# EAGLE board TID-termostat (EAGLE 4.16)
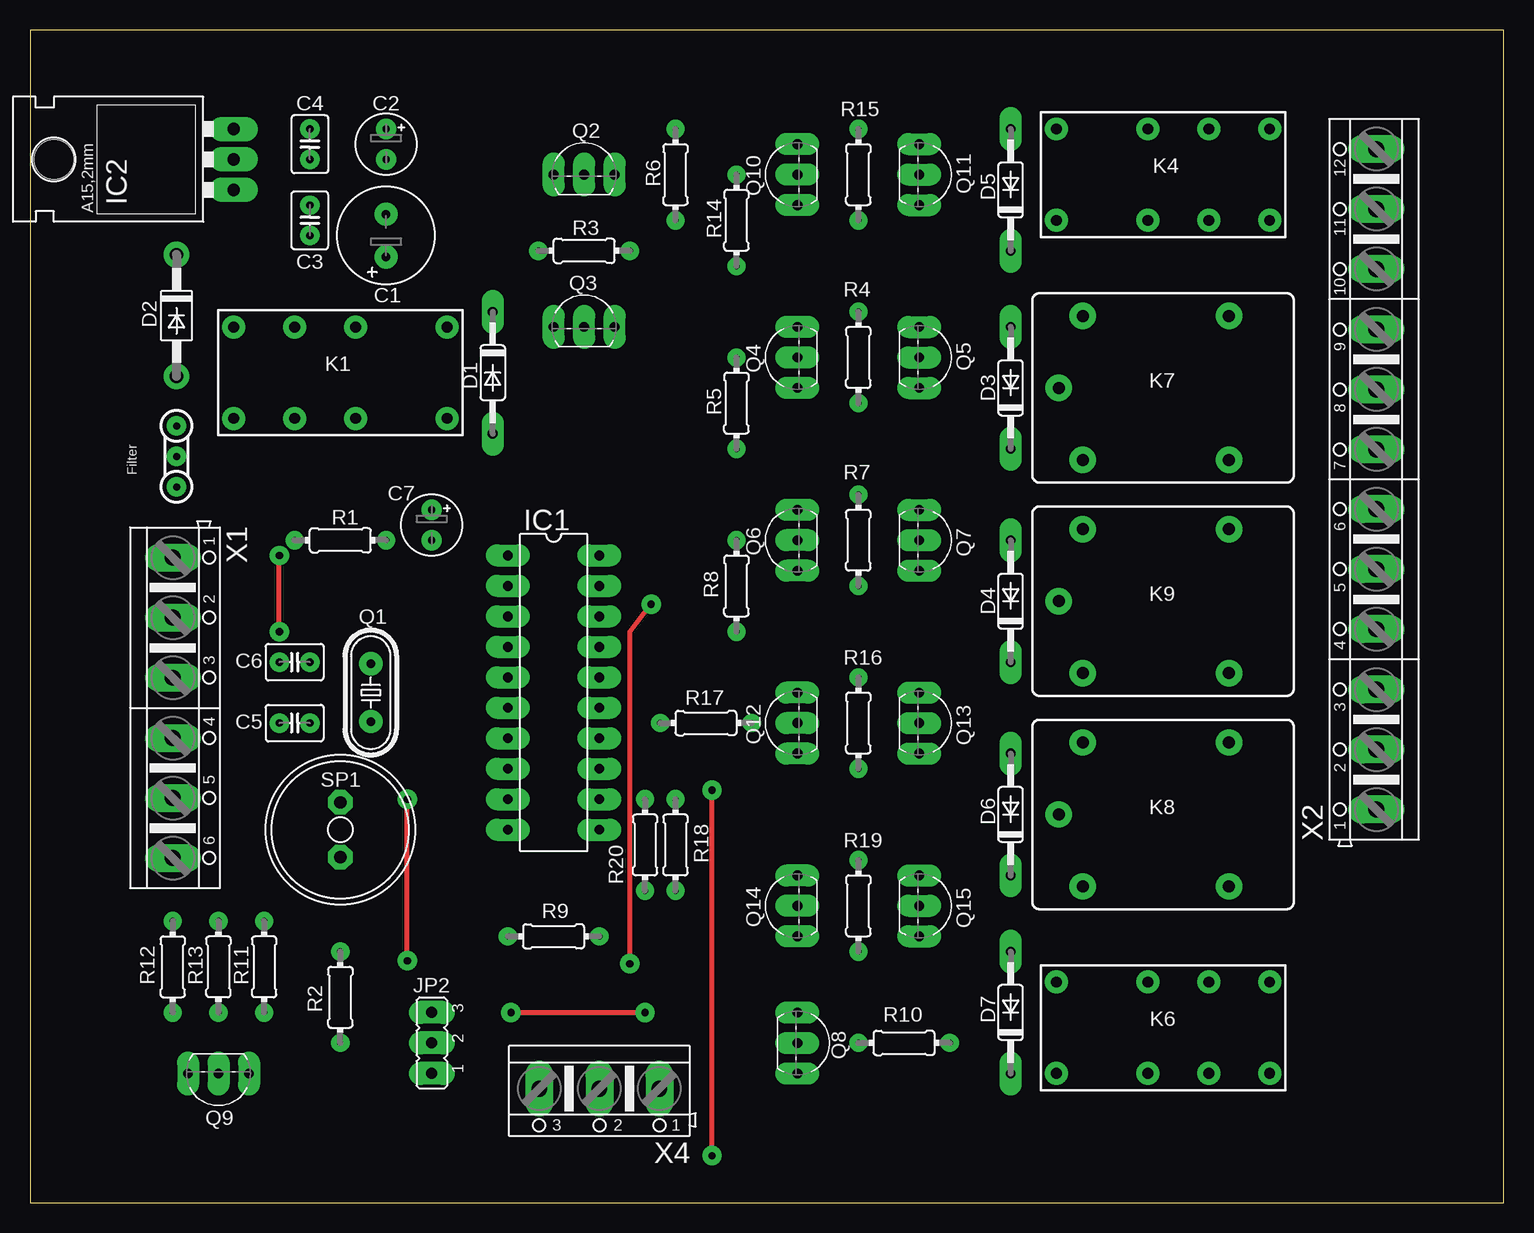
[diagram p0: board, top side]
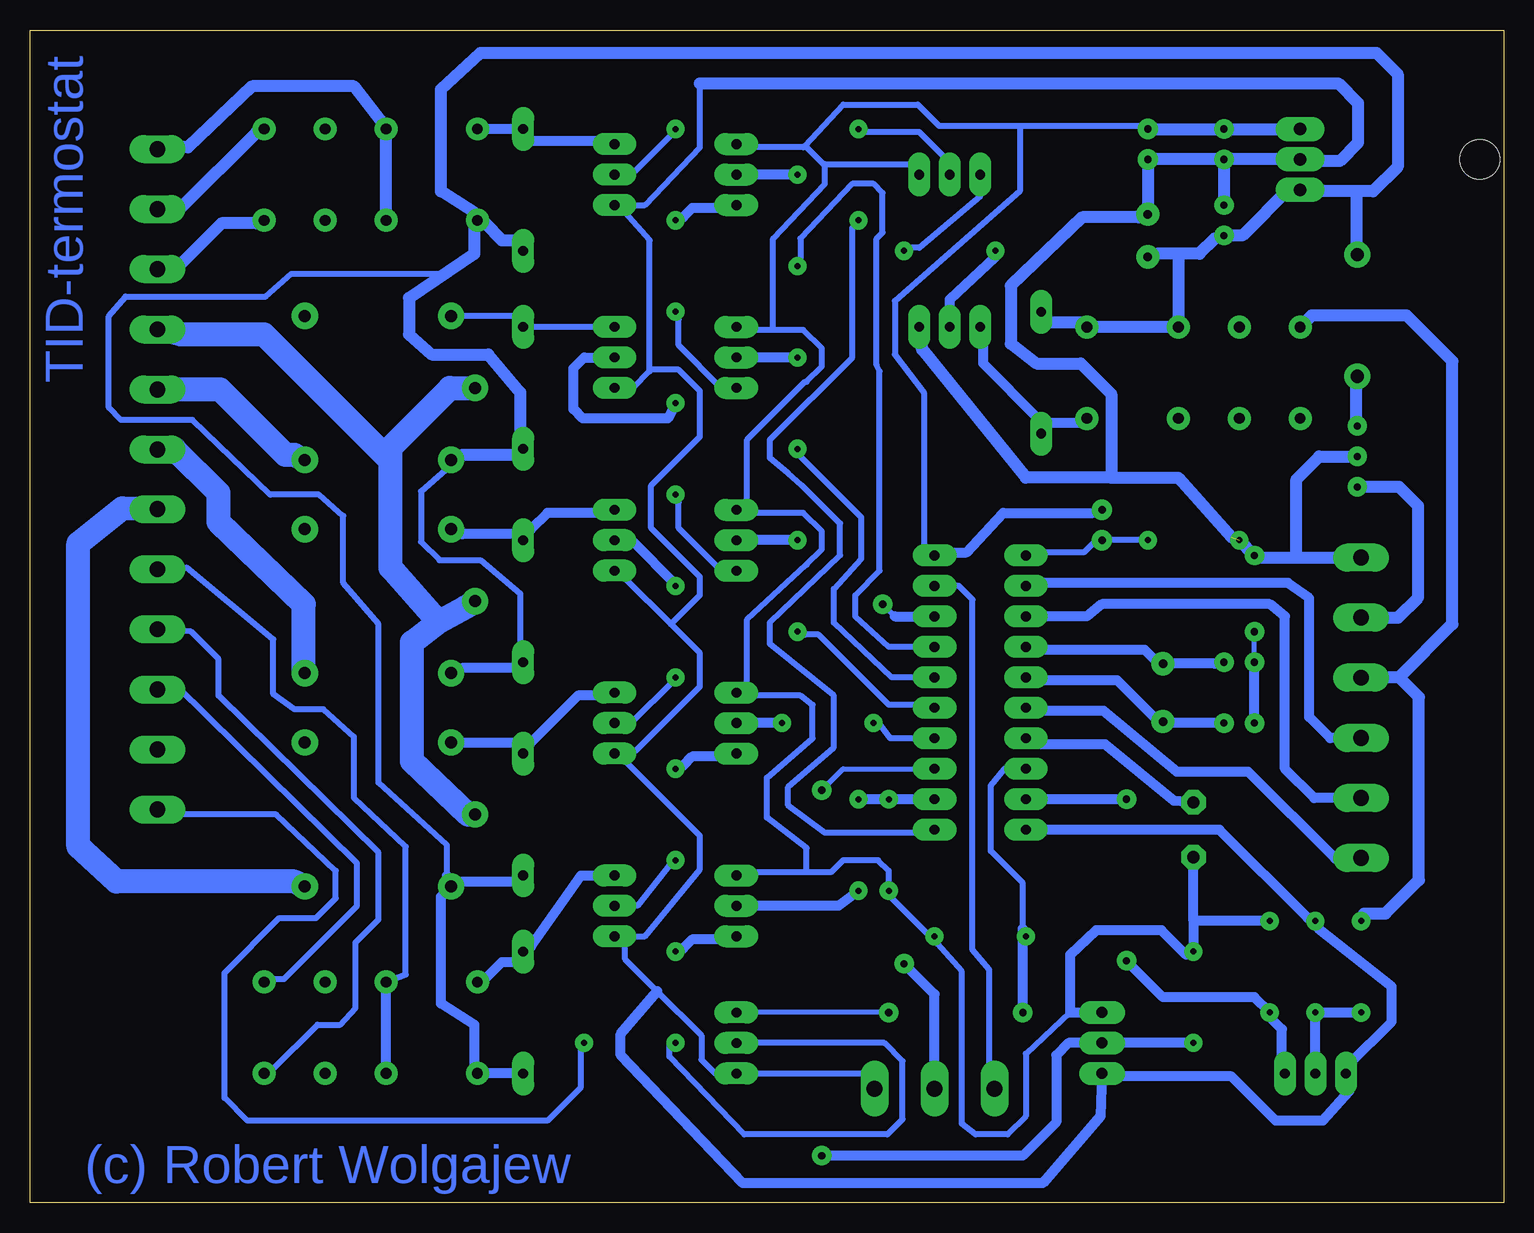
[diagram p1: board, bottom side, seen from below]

Size 122.86 x 97.78 mm. Coordinates in mm from the lower left corner, seen from the top.
Outline: 0,0 122.86,0 122.86,97.78 0,97.78 0,0
Copper layers (1*16): Top 0.035mm / dielectric 1.5mm / Bottom 0.035mm
Design rules "default": minimum track width 20mil, minimum drill 24mil, track to track 40mil, track to pad 40mil, pad to pad 40mil, via to via 40mil, smd to smd 8mil, copper to edge 20mil, drill to drill 25mil, minimum pad ring 20mil, minimum via ring 20mil, stop-mask expansion 4mil, vias tented up to drill 0mil, thermal gap 10mil
Net classes: 1 moja: width 2 mm, clearance 1 mm

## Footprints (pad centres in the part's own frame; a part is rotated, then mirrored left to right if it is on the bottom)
E3,5-8 = drill 0.7 pad 1.93 round: + -1.778,0; - 1.778,0
E2,5-5 = drill 0.6 pad 1.676 round: + -1.27,0; - 1.27,0
C2.5-3 = drill 0.6 pad 1.6 round: 1 -1.27,0; 2 1.27,0
DO35-10 = drill 0.813 long: A 5.08,0; C -5.08,0
DO41-10 = drill 1.118 round: A 5.08,0; C -5.08,0
FILTRDSS = drill 0.6 pad 1.422 round: GND -8.89,5.08; IN -11.43,5.08; OUT -6.35,5.08
DIL20 = drill 0.813 long: 1 -11.43,-3.81; 2 -8.89,-3.81; 3 -6.35,-3.81; 4 -3.81,-3.81; 5 -1.27,-3.81; 6 1.27,-3.81; 7 3.81,-3.81; 8 6.35,-3.81; 9 8.89,-3.81; 10 11.43,-3.81; 11 11.43,3.81; 12 8.89,3.81; 13 6.35,3.81; 14 3.81,3.81; 15 1.27,3.81; 16 -1.27,3.81; 17 -3.81,3.81; 18 -6.35,3.81; 19 -8.89,3.81; 20 -11.43,3.81
78XXL = drill 1.016 long: GND 0,-3.81; IN -2.54,-3.81; OUT 2.54,-3.81 | hole 3.302: 0,11.176
JP2 = drill 0.914 long: 1 -2.54,0; 2 0,0; 3 2.54,0
DS-BT = drill 0.9 round: 1 -8.89,-3.81; 4 -1.27,-3.81; 6 3.81,-3.81; 8 8.89,-3.81; 9 8.89,3.81; 11 3.81,3.81; 13 -1.27,3.81; 16 -8.89,3.81
JS-M = drill 1 pad 2.184 round: 1 6.7,6; 2 6.7,-6; C 8.7,0; NC -5.5,-6; NO -5.5,6
HC49/S = drill 0.7 pad 1.93 round: 1 -2.413,0; 2 2.413,0
TO92-EBC = drill 0.813 long: B 0,-1.27; C -2.54,-1.27; E 2.54,-1.27
0204/7 = drill 0.5 pad 1.499 round: 1 -3.81,0; 2 3.81,0
AL11P = drill 1.016 pad 1.905 octagon: + 2.286,0; - -2.286,0
AK500/6 = drill 1.321 long: 1 -12.522,0; 2 -7.518,0; 3 -2.515,0; 4 2.515,0; 5 7.518,0; 6 12.522,0
AK500/12 = drill 1.321 long: 1 -27.534,0; 2 -22.53,0; 3 -17.526,0; 4 -12.497,0; 5 -7.493,0; 6 -2.489,0; 7 2.489,0; 8 7.493,0; 9 12.497,0; 10 17.526,0; 11 22.53,0; 12 27.534,0
AK500/3 = drill 1.321 long: 1 -5.004,0; 2 0,0; 3 5.004,0

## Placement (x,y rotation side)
C1  470uF  [E3,5-8]  29.68,80.64 90 top
C2  220uF  [E2,5-5]  29.68,88.26 270 top
C3  100nF  [C2.5-3]  23.33,81.91 90 top
C4  100nF  [C2.5-3]  23.33,88.26 270 top
C5  33pF  [C2.5-3]  22.06,40 0 top
C6  33pF  [C2.5-3]  22.06,45.08 0 top
C7  10uF  [E2,5-5]  33.49,56.51 270 top
D1  1N4148  [DO35-10]  38.57,69.21 270 top
D2  1N4004  [DO41-10]  12.22,73.97 270 top
D3  1N4148  [DO35-10]  81.75,67.94 90 top
D4  1N4148  [DO35-10]  81.75,50.16 90 top
D5  1N4148  [DO35-10]  81.75,84.45 90 top
D6  1N4148  [DO35-10]  81.75,32.38 90 top
D7  1N4148  [DO35-10]  81.75,15.87 90 top
FT1  DSS306-55F223  [FILTRDSS]  17.3,71.11 90 top
IC1  AT89C4051P  [DIL20]  43.65,42.54 270 top
IC2  7805  [78XXL]  13.17,86.99 90 top
JP2  DS1820  [JP2]  33.49,13.33 90 top
K1  Wewn_AA  [DS-BT]  25.87,69.21 180 top
K4  Klima  [DS-BT]  94.45,85.72 0 top
K6  Swiatla  [DS-BT]  94.45,14.6 0 top
K7  Stopien 1  [JS-M]  94.45,67.94 180 top
K8  Stopien 3  [JS-M]  94.45,32.38 180 top
K9  Stopien 2  [JS-M]  94.45,50.16 180 top
Q1  11.0592 MHz  [HC49/S]  28.41,42.54 270 top
Q2  BC560  [TO92-EBC]  46.19,86.99 0 top
Q3  BC548  [TO92-EBC]  46.19,74.29 0 top
Q4  BC560  [TO92-EBC]  62.7,70.48 90 top
Q5  BC548  [TO92-EBC]  75.4,70.48 270 top
Q6  BC560  [TO92-EBC]  62.7,55.24 90 top
Q7  BC548  [TO92-EBC]  75.4,55.24 270 top
Q8  BC548  [TO92-EBC]  65.24,13.33 270 top
Q9  BC548  [TO92-EBC]  15.71,9.52 180 top
Q10  BC560  [TO92-EBC]  62.7,85.72 90 top
Q11  BC548  [TO92-EBC]  75.4,85.72 270 top
Q12  BC560  [TO92-EBC]  62.7,40 90 top
Q13  BC548  [TO92-EBC]  75.4,40 270 top
Q14  BC560  [TO92-EBC]  62.7,24.76 90 top
Q15  BC548  [TO92-EBC]  75.4,24.76 270 top
R1  10K  [0204/7]  25.87,55.24 0 top
R2  4.7K  [0204/7]  25.87,17.14 270 top
R3  2.2K  [0204/7]  46.19,79.37 0 top
R4  2.2K  [0204/7]  69.05,70.48 90 top
R5  2.2K  [0204/7]  58.89,66.67 270 top
R6  2.2K  [0204/7]  53.81,85.72 270 top
R7  2.2K  [0204/7]  69.05,55.24 90 top
R8  2.2K  [0204/7]  58.89,51.43 270 top
R9  1K  [0204/7]  43.65,22.22 180 top
R10  10K  [0204/7]  72.86,13.33 180 top
R11  1K  [0204/7]  19.52,19.68 90 top
R12  10K  [0204/7]  11.9,19.68 270 top
R13  4.7K  [0204/7]  15.71,19.68 90 top
R14  2.2K  [0204/7]  58.89,81.91 270 top
R15  2.2K  [0204/7]  69.05,85.72 270 top
R16  2.2K  [0204/7]  69.05,40 270 top
R17  2.2K  [0204/7]  56.35,40 180 top
R18  2.2K  [0204/7]  53.81,29.84 90 top
R19  2.2K  [0204/7]  69.05,24.76 270 top
R20  1K  [0204/7]  51.27,29.84 90 top
SP1  Buzzer  [AL11P]  25.87,31.11 270 top
X1  [AK500/6]  11.9,41.27 270 top
X2  [AK500/12]  112.23,60.32 90 top
X4  [AK500/3]  47.46,9.52 180 top

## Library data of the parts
C1 C2 C7 R1-R20 = rcl
C3-C6 = capacitor-wima
D1-D7 = diode
FT1 = filtrDSS
IC1 = atmel
IC2 = v-reg
JP2 = jumper
K1 K4 K6-K9 = relay
Q1 = crystal
Q2 Q4 Q6 Q10 Q12 Q14 = transistor-pnp
Q3 Q5 Q7-Q9 Q11 Q13 Q15 = transistor-npn
SP1 = buzzer
X1 X2 X4 = con-ptr500

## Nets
N$1: IC1.9 Q9.C R11.1
N$2: C2.+ C4.1 C7.+ IC1.20 IC2.OUT JP2.3 Q2.E Q4.E Q6.E Q10.E Q12.E Q14.E R2.1 R9.1 R11.2 R20.1 SP1.+
N$3: Q2.B R6.1
N$4: IC1.13 JP2.2 R2.2
N$5: D1.A K1.16 Q3.C
N$6: C5.2 IC1.5 Q1.2
N$7: C6.2 IC1.4 Q1.1
N$8: IC1.7 SP1.-
N$9: C7.- IC1.1 R1.2
N$10: IC1.8 Q8.C R9.2
N$11: IC1.19 X4.3
N$12: Q2.C R3.2
N$13: Q3.B R3.1
N$14: Q10.B R14.1
N$15: IC1.18 X4.2
N$16: IC1.11 R6.2
N$17: Q10.C R15.2
N$18: Q11.B R15.1
N$19: Q4.C R4.2
N$20: Q5.B R4.1
N$21: Q4.B R5.1
N$22: D3.A K7.2 Q5.C
N$23: C1.+ C3.1 D1.C D2.C D3.C D4.C D5.C D6.C D7.C IC2.IN K1.1 K1.4 K4.1 K6.1 K7.1 K8.1 K9.1
N$24: K4.8 X2.10
N$25: Q6.C R7.2
N$26: Q7.B R7.1
N$27: Q6.B R8.1
N$28: D4.A K9.2 Q7.C
N$29: Q8.B R10.2
N$30: K4.9 X2.11
N$31: Q9.B R12.2 R13.1
N$32: D5.A K4.16 Q11.C
N$33: C1.- C2.- C3.2 C4.2 C5.1 C6.1 FT1.GND IC1.10 IC2.GND JP2.1 Q3.E Q5.E Q7.E Q8.E Q9.E Q11.E Q13.E Q15.E R1.1 R13.2 X1.1 X4.1
N$34: D2.A FT1.OUT
N$35: Q12.B R17.1
N$36: Q12.C R16.2
N$37: Q13.B R16.1
N$38: K6.8 X2.4
N$39: D6.A K8.2 Q13.C
N$40: K6.9 X2.3
N$41 [moja]: K7.NO X2.8
N$42 [moja]: K9.NO X2.7
N$43 [moja]: K8.NO X2.6
N$44: IC1.16 R5.2
N$45: IC1.15 R8.2
N$46: IC1.14 R17.2
N$47 [moja]: K7.C K8.C K9.C X2.9
N$48: K4.4 K4.13 X2.12
N$49: IC1.17 R14.2
N$50: K1.8 R12.1 X1.3
N$51: IC1.2 X1.4
N$52: IC1.3 X1.5
N$53: IC1.6 X1.6
N$54: R10.1 X2.1
N$55: FT1.IN X1.2
N$56: Q14.B R18.1
N$57: Q14.C R19.2
N$58: Q15.B R19.1
N$59: D7.A K6.16 Q15.C
N$61: K6.4 K6.13 X2.5
N$63: IC1.12 R18.2 R20.2

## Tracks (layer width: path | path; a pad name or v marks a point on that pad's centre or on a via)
N$1  (via drill 0.6 pad 0.61)
  Top 0.406: v31.46,20.19 v31.46,33.65
  Bottom 0.508: 19.27,15.23 R11.1
  Bottom 0.813: 19.27,15.23 18.5,14.47 18.5,12.06 Q9.C | R11.1 20.79,17.14 28.41,17.14 v31.46,20.19 | v31.46,33.65 IC1.9
N$2
  Bottom 0.508: R2.1 26.51,20.7 | 58.13,27.55 56.1,27.55 55.08,28.57 52.16,28.57 51.27,27.68 R20.1 51.02,25.39 48.09,22.47 R9.1 47.21,21.59 45.17,19.3 45.17,6.6 44.03,5.71 41.36,5.71 39.84,7.23 39.84,12.44 36.16,15.87 | 58.13,27.55 62.7,27.55 Q14.E | 58.13,27.55 58.13,29.59 61.43,32.13 61.43,35.43 57.62,38.73 57.62,41.52 58.64,42.29 62.7,42.29 Q12.E 63.08,43.17 63.08,48.64 58.13,53.21 56.86,54.48 56.86,56 58.38,57.53 62.7,57.53 Q6.E 63.08,58.42 63.08,63.62 58.25,68.45 58.13,68.45 56.86,69.72 56.86,71.24 58.38,72.77 60.92,72.77 | 60.92,72.77 62.7,72.77 Q4.E | 46.19,54.22 IC1.20 48.35,54.61 48.35,67.56 50.76,70.73 50.76,75.18 40.35,84.32 40.35,89.78 | 56.6,86.61 56.73,86.61 58.25,88.13 | 56.6,86.61 49.37,86.61 Q2.E | 58.25,88.13 58.38,88.01 62.7,88.01 Q10.E | 40.35,89.78 47.08,89.78 48.86,91.56 55.08,91.56 58.25,88.13 | 40.35,89.78 30.44,89.78 C2.+ | 60.92,72.77 60.92,80.39 56.6,84.96 56.6,86.61
  Bottom 0.813: 25.87,23.49 R2.1 | 25.87,23.49 SP1.+ | R11.2 25.87,23.49 | 26.51,20.7 28.54,22.73 34,22.73 36.16,20.7 36.16,15.87 JP2.3 | 46.19,54.22 44.79,54.22 41.74,57.53 34.25,57.53 C7.+
  Bottom 1.016: IC2.OUT C4.1 C2.+
N$3
  Bottom 0.508: Q2.B 46.44,86.99 48.73,89.28 53.17,89.28 R6.1
N$4  (via drill 0.6 pad 0.61)
  Top 0.406: v56.86,3.93 v56.86,34.41
  Bottom 0.406: IC1.13 55.08,36.19 v56.86,34.41
  Bottom 0.813: R2.2 JP2.2 36.28,13.33 37.3,12.31 37.3,6.73 40.09,3.93 v56.86,3.93
N$5
  Bottom 0.508: 37.94,65.02 D1.A 38.82,65.4 | 35.27,65.02 K1.16 | 43.4,71.75 Q3.C
  Bottom 0.813: 35.27,65.02 37.94,65.02 | 43.4,71.75 43.4,69.97 38.82,65.4
N$6
  Bottom 0.508: 27.77,40 Q1.2 29.05,40.38 | 38.57,43.56 IC1.5
  Bottom 0.813: C5.2 27.77,40 | 38.57,43.56 32.22,43.56 29.05,40.38
N$7
  Bottom 0.508: 24.09,44.95 C6.2 | Q1.1 29.05,45.21
  Bottom 0.813: 24.09,44.95 Q1.1 | 29.05,45.21 29.93,46.1 38.57,46.1 IC1.4
N$8
  Bottom 0.508: 38.57,38.22 IC1.7
  Bottom 0.813: 38.57,38.22 33.24,38.22 27.52,33.52 SP1.-
N$9
  Bottom 0.508: R1.2 C7.- 34.25,54.99 35.01,54.22 38.57,54.22 IC1.1
N$10  (via drill 0.6 pad 0.61)
  Top 0.406: v40.09,15.87 v51.27,15.87
  Bottom 0.406: v51.27,15.87 Q8.C
  Bottom 0.508: R9.2 40.09,22.86 40.09,26.66 42.76,29.33 42.76,34.79 41.62,36.19 IC1.8
  Bottom 0.813: v40.09,15.87 40.09,22.86
N$11
  Bottom 0.508: IC1.19 45.43,51.43 44.28,50.29 44.28,21.08 42.89,19.43 42.89,11.42 X4.3
N$12
  Bottom 0.508: R3.2 49.37,79.62 48.73,79.62 43.65,83.94 Q2.C
N$13
  Bottom 0.508: 42.38,78.86 R3.1
  Bottom 0.813: 42.38,78.86 46.19,75.31 Q3.B
N$14
  Bottom 0.813: R14.1 Q10.B
N$15  (via drill 0.6 pad 0.61)
  Top 0.406: v50,19.93 50,47.62 v51.78,49.91
  Bottom 0.406: IC1.18 47.21,48.89 | v51.78,49.91 50.76,48.89
  Bottom 0.813: X4.2 47.46,17.39 v50,19.93 | 50.76,48.89 IC1.18
N$16
  Bottom 0.406: 54.32,70.48 54.32,70.61
  Bottom 0.508: IC1.11 47.21,30.86 56.6,30.86 59.65,33.14 59.65,34.67 55.84,37.97 55.84,42.29 61.18,46.6 61.18,48.38 55.33,53.97 55.33,56.64 58.51,59.81 59.65,60.83 61.18,62.1 61.18,63.62 54.32,70.48 | 54.32,70.61 54.32,81.27 R6.2
N$17
  Bottom 0.508: Q10.C 65.24,82.93
  Bottom 0.813: 65.24,82.93 67.65,82.93 68.42,82.16 R15.2
N$18
  Bottom 0.508: R15.1 68.92,89.53 72.73,85.72 Q11.B
N$19
  Bottom 0.508: Q4.C 65.24,67.94 68.8,71.5 68.8,73.66 R4.2
N$20
  Bottom 0.813: R4.1 69.69,65.4 76.8,65.4 77.56,66.16 77.56,69.59 76.67,70.48 Q5.B
N$21
  Bottom 0.813: R5.1 Q4.B
N$22
  Bottom 0.508: Q5.C D3.A 82.39,73.91 86.83,73.91 K7.2
N$23
  Bottom 0.508: C3.1 24.09,80.39 | 17.87,84.58 IC2.IN 16.6,84.32 | 82.39,26.79 D6.C | K8.1 86.83,26.79 | K6.1 85.81,11.42 | 82.39,44.57 D4.C 82,46.35 82,50.8 85.31,53.59 88.73,53.59 90.26,55.11 90.26,59.3 88.23,61.08 K7.1 86.83,62.35 | 82.39,80.26 D5.C | 84.93,81.66 K4.1 85.81,82.55 | 82,64.13 D3.C | 88.1,27.3 88.1,29.84 93.82,35.05 93.82,48.25 96.74,51.68 96.74,57.27 98.77,59.05 102.83,59.05 109.31,65.27 115.28,65.27 116.29,66.29 116.29,73.91 114.9,75.56 103.21,75.56 101.05,77.46 88.23,77.46 85.81,79.12
  Bottom 0.813: D7.C K6.1 | 86.83,26.79 82.39,26.79 | 85.81,11.42 85.81,14.85 88.61,16.63 88.61,25.52 K8.1 88.1,27.3 | 82.39,44.57 86.83,44.57 K9.1
  Bottom 1.016: D1.C 37.94,73.4 35.27,73.4 K1.1 K1.4 27.14,79.12 | 27.14,79.12 25.36,79.12 24.09,80.39 | 27.14,79.12 28.92,79.12 C1.+ | 17.87,84.58 21.81,80.64 C3.1 | 82.39,80.26 83.53,80.26 84.93,81.66 | 86.83,62.35 82.39,62.35 D3.C | 82,64.13 82,67.56 84.67,70.73 89.37,70.73 91.28,72.39 91.28,75.43 85.81,79.12 85.81,81.27 K4.1 | 12.28,84.32 10.88,84.32 8.85,86.35 8.85,94.1 10.63,95.88 85.31,95.88 88.61,92.83 88.61,84.32 85.81,82.55 | 12.28,84.32 16.6,84.32 | D2.C 12.28,79.88 12.28,84.32
N$24
  Bottom 1.016: K4.8 103.98,81.66 106.9,81.66 110.33,78.23 X2.10
N$25
  Bottom 0.508: Q6.C 65.24,52.7 68.8,56.26 68.8,58.42 R7.2
N$26
  Bottom 0.508: R7.1 68.92,51.43 | 72.73,55.24 Q7.B
  Bottom 0.813: 68.92,51.43 72.73,55.24
N$27
  Bottom 0.813: R8.1 Q6.B
N$28
  Bottom 0.813: K9.2 86.83,55.75 82.39,55.75 D4.A 81.12,56.13 79.72,57.53 75.4,57.53 Q7.C
N$29
  Bottom 0.508: 64.22,13.33 Q8.B 51.65,13.33 50.13,11.81 50.13,6.98 51.4,5.71 63.34,5.71 69.56,12.19 69.56,13.33 R10.2
N$30
  Bottom 1.016: K4.9 103.98,89.28 110.33,82.93 X2.11
N$31
  Bottom 0.813: Q9.B R13.1 R12.2
N$32
  Bottom 0.508: Q11.C 74.89,88.51 | 81.24,88.51 D5.A
  Bottom 0.813: 74.89,88.51 81.24,88.51 | D5.A K4.16
N$33  (via drill 0.6, 0.6 pad 0.61)  (1 unrouted)
  Top 0.406: v20.79,47.62 v20.79,53.97
  Bottom 0.406: C6.1 v20.79,47.62
  Bottom 0.508: C1.- 30.44,82.16 | 12.92,11.55 Q9.E 12.92,9.27 | 15.46,22.86 R13.2 16.34,23.74 | 32.09,10.54 JP2.1 | X4.1 53.43,10.79 Q8.E 65.75,10.79 66.89,11.93 66.89,13.96 70.57,17.65 73.24,20.31 73.24,21.59 Q15.E 71.59,22.22 67.02,27.81 67.02,30.6 73.24,36.83 Q13.E 72.86,37.71 72.35,37.71 67.02,43.05 67.02,45.84 69.43,48.25 | 71.21,69.34 72.61,67.94 Q5.E | 71.21,69.34 71.21,80.26 73.24,82.55 Q11.E 71.59,83.18 67.02,88.01 67.02,93.34 | 69.43,48.25 73.24,52.06 Q7.E | 71.21,69.34 71.08,69.46 68.8,69.46 67.02,67.69 67.02,63.88 71.08,59.81 71.08,56.26 67.02,52.19 67.02,50.67 69.43,48.25 | 16.85,86.86 IC2.GND
  Bottom 0.813: C5.1 C6.1 | 12.92,11.55 9.36,15.11 9.36,18.03 15.46,22.86 | 16.34,23.74 23.71,31.11 IC1.10 | 32.09,10.54 22.7,10.54 19.01,6.85 15.07,6.85 12.92,9.27 | JP2.1 33.62,7.23 38.44,1.65 63.46,1.65 73.62,12.31 73.62,14.09 70.57,17.65
  Bottom 1.016: C1.- C2.- C4.2 | C4.2 C3.2 | IC2.GND C4.2 | 32.73,60.45 27.14,60.45 22.7,55.49 | 32.73,60.45 39.84,60.45 48.48,71.11 48.73,72.26 Q3.E | 30.44,82.16 35.14,82.16 41.11,76.45 41.11,71.62 38.95,69.97 35.27,69.97 32.73,67.43 32.73,60.45 | 16.85,86.86 13.68,86.86 12.15,88.39 12.15,91.69 13.8,93.34 67.02,93.34 | 17.3,53.79 20.79,53.79 v20.79,53.97 R1.1 | 17.3,53.79 X1.1 | FT1.GND 15.39,62.22 17.3,60.32 17.3,53.79
N$34
  Bottom 1.016: FT1.OUT 12.28,65.4 12.28,68.07 D2.A
N$35
  Bottom 0.813: R17.1 Q12.B
N$36
  Bottom 0.813: Q12.C 65.24,37.21 67.65,37.21 68.42,36.44 R16.2
N$37
  Bottom 0.508: R16.1 68.92,43.81 72.99,39.75 Q13.B
N$38
  Bottom 0.508: K6.8 102.71,11.04 98.9,14.85 96.99,14.85 95.72,16.25 95.72,21.71 93.82,23.62 93.82,29.2 107.15,42.29 107.15,45.33 109.44,47.62 X2.4
N$39
  Bottom 0.508: D6.A 82.39,38.35
  Bottom 0.813: Q13.C 75.4,42.29 77.18,42.29 81.12,38.35 D6.A | 82.39,38.35 86.83,38.35 K8.2
N$40
  Bottom 0.508: K6.9 102.71,18.66 101.69,18.66 95.59,24.76 95.59,28.32 110.58,43.05 X2.3
N$41
  Bottom 2: K7.NO 100.8,62.35 101.56,62.35 107.02,67.81 X2.8
N$42
  Bottom 2: K9.NO 100.04,44.32 100.04,49.91 107.15,56.76 107.15,59.18 110.83,62.86 X2.7
N$43
  Bottom 2: K8.NO 100.8,26.79 115.66,26.79 118.83,29.71 118.83,54.99 115.15,57.91 X2.6
N$44
  Bottom 0.508: IC1.16 51.02,43.81 55.84,48.38 55.84,51.18 53.56,53.72 53.56,57.14 58.64,62.22 R5.2
N$45
  Bottom 0.508: IC1.15 48.73,41.52 51.27,41.52 57.11,47.37 58.25,47.37 R8.2
N$46
  Bottom 0.508: IC1.14 51.14,38.73 51.91,39.75 R17.2
N$47
  Bottom 2: 88.8,48.44 86.58,49.65 K9.C | 88.8,48.44 91.02,46.73 91.02,36.83 86.32,32.38 K8.C | 92.8,62.99 87.85,67.94 K7.C | 92.8,62.99 92.8,52.95 88.8,48.44 | X2.9 110.33,72.39 103.34,72.39 93.18,62.22 92.8,62.99
N$48
  Bottom 1.016: K4.4 K4.13 93.31,89.78 95.85,93.09 104.36,93.09 109.69,88.01 112.36,88.01 X2.12
N$49
  Bottom 0.508: IC1.17 51.27,46.35 54.06,48.89 54.06,50.67 52.03,52.7 52.03,69.34 52.29,69.84 52.29,80.39 51.78,80.89 51.78,84.2 52.54,84.96 54.32,84.96 58.64,80.39 58.64,78.73 R14.2
N$50
  Bottom 1.016: R12.1 11.65,24.12 9.87,24.12 7.07,26.92 7.07,42.16 8.73,43.81 | X1.3 11.9,43.81 8.73,43.81 | 8.73,43.81 4.28,48.25 4.28,70.16 8.09,73.97 16.03,73.97 K1.8
N$51
  Bottom 0.813: X1.4 14.46,38.75 16.22,40.51 16.22,50.41 18,51.68 39.59,51.68 IC1.2
N$52
  Bottom 0.813: X1.5 15.81,33.75 18.25,36.19 18.25,48.89 19.52,49.91 33.49,49.91 34.76,48.89 IC1.3
N$53
  Bottom 0.508: 38.57,41.02 IC1.6
  Bottom 0.813: 38.57,41.02 33.36,41.02 27.27,35.94 21.3,35.94 14.06,28.7 X1.6
N$54
  Bottom 0.508: R10.1 76.92,12.7 76.92,9.65 79.72,6.85 104.74,6.85 106.64,8.76 106.64,19.17 102.07,23.74 99.02,23.74 97.37,25.39 97.37,27.68 102.32,32.38 110.33,32.38 X2.1
N$55
  Bottom 1.016: X1.2 8.83,48.79 7.14,50.48 7.14,58.1 8.73,59.69 FT1.IN
N$56
  Bottom 0.508: Q14.B 62.7,25.01
  Bottom 0.813: Q14.B 55.46,24.76 R18.1
N$57
  Bottom 0.813: Q14.C 65.24,21.97 67.65,21.97 68.42,21.2 R19.2
N$58
  Bottom 0.508: R19.1 69.43,28.32 72.23,24.76 Q15.B
N$59
  Bottom 0.508: 82.39,20.06 D7.A 81.12,21.33
  Bottom 0.813: 82.39,20.06 83.53,20.06 84.93,18.66 K6.16 | 81.12,21.33 76.92,27.3 Q15.C
N$61
  Bottom 0.508: X2.5 109.82,52.95 102.58,46.98 102.58,42.41 100.8,41.14 98.39,41.14 95.85,38.86 95.85,33.78 91.53,29.71 91.53,19.05 K6.13
  Bottom 0.813: K6.4 K6.13
N$63
  Bottom 0.813: IC1.12 R20.2 R18.2

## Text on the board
Bottom: TID-termostat | (c) Robert Wolgajew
